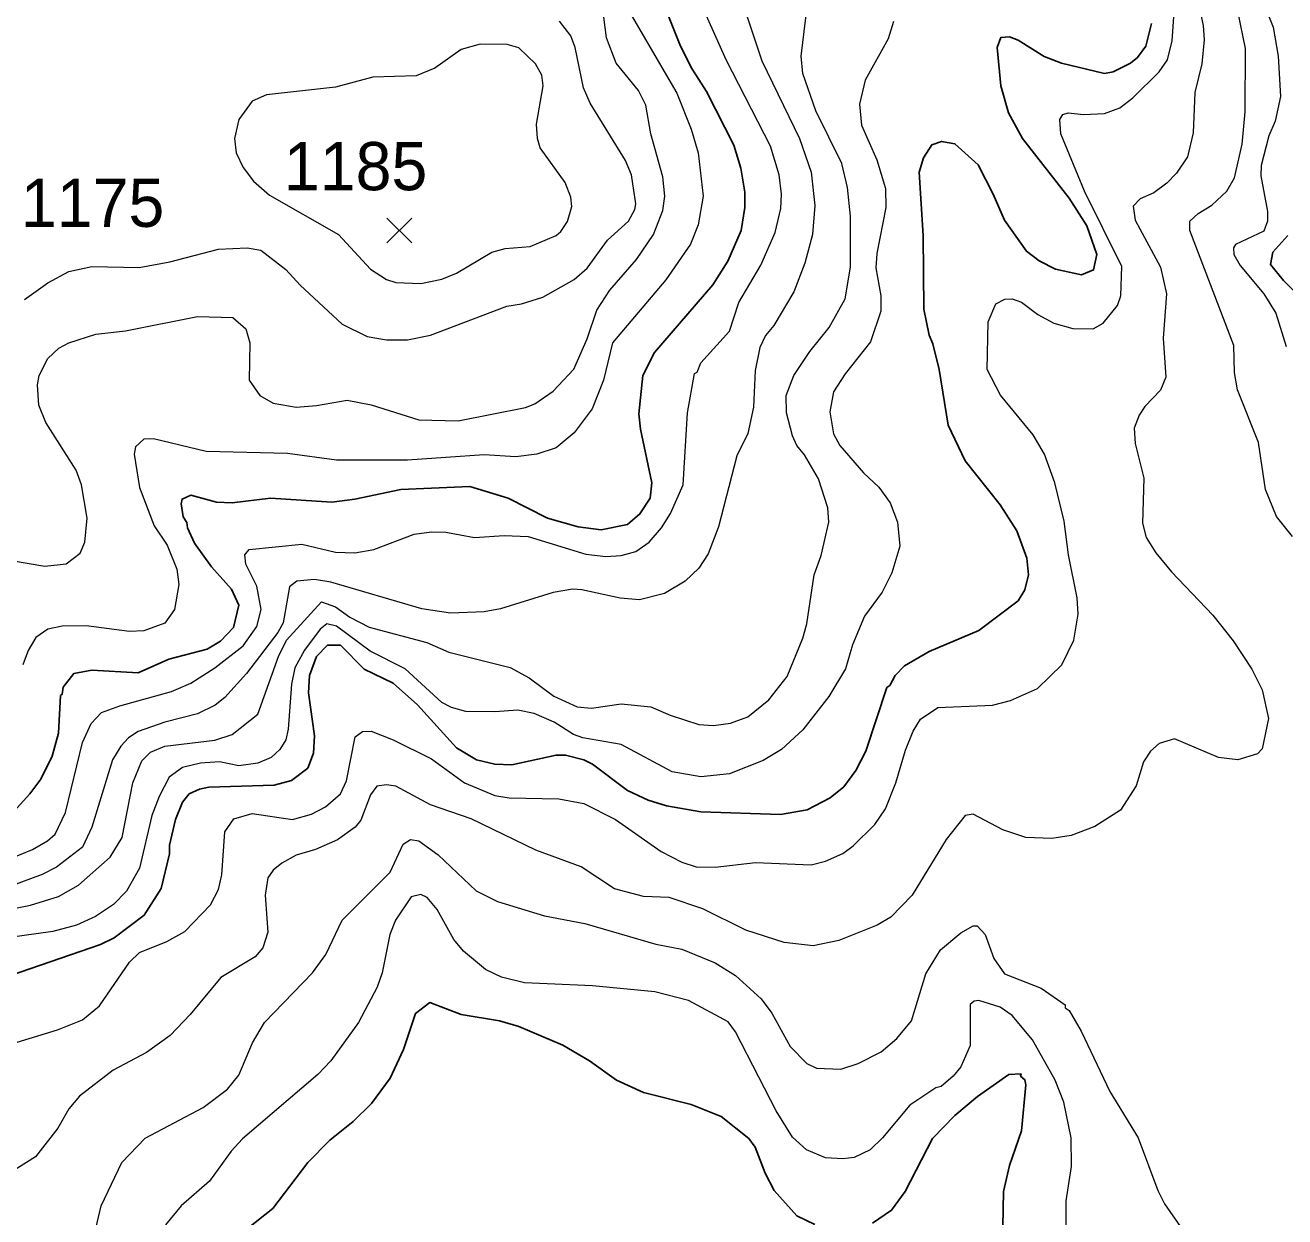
# Model space of a CAD drawing. Extents: x 265 to 291.4, y 7731.5 to 7759.6.
# Drawn here: x 287.12 to 289.21, y 7740.103 to 7742.081 of the extents above; entities that cross this region are included whole.
import ezdxf
from ezdxf.enums import TextEntityAlignment as Align

# ---------------------------------------------------------------- set-up
doc = ezdxf.new("R2010")
doc.units = 0
doc.header["$LTSCALE"] = 0.032
for name, color, linetype, lineweight in [('1', 7, 'Continuous', 25), ('2', 7, 'Continuous', 13), ('21', 7, 'Continuous', 25), ('61', 7, 'Continuous', 13)]:
    doc.layers.add(name, color=color, linetype=linetype, lineweight=lineweight)

msp = doc.modelspace()

# ---------------------------------------------------------------- linework, layer by layer
at = {"layer": '1'}
for points in [[(288.1811, 7742.1121), (288.2065, 7742.0485), (288.2256, 7742.0103), (288.2511, 7741.9705), (288.2964, 7741.8814), (288.3076, 7741.8432)], [(287.5908, 7740.973), (287.5924, 7741.0016), (287.6036, 7741.0334), (287.6219, 7741.0517), (287.6434, 7741.0517), (287.6831, 7741.0119), (287.7309, 7740.9888), (287.7714, 7740.9531), (287.8359, 7740.8815), (287.8693, 7740.8616), (287.8995, 7740.8544), (287.9281, 7740.8536), (288.0013, 7740.8695), (288.0172, 7740.8695), (288.0475, 7740.8616), (288.0618, 7740.8544), (288.1199, 7740.8106), (288.1541, 7740.7947), (288.1843, 7740.7852), (288.2416, 7740.7756), (288.3736, 7740.7709), (288.4182, 7740.7788), (288.4563, 7740.7987), (288.4786, 7740.817), (288.4985, 7740.8441), (288.5152, 7740.8759), (288.5502, 7740.9817), (288.555, 7740.9849), (288.5637, 7741.0016), (288.5796, 7741.0175), (288.6202, 7741.0413), (288.703, 7741.0763), (288.7682, 7741.1257), (288.7793, 7741.144), (288.7849, 7741.1686), (288.7825, 7741.1965), (288.7658, 7741.2418), (288.7379, 7741.2848), (288.6799, 7741.358), (288.652, 7741.4168), (288.6369, 7741.5091), (288.6266, 7741.5521), (288.6202, 7741.5664), (288.6114, 7741.6093), (288.6106, 7741.7318), (288.6035, 7741.8369), (288.6107, 7741.8607), (288.625, 7741.8822), (288.6409, 7741.8877), (288.6632, 7741.8838), (288.7014, 7741.8488), (288.7268, 7741.8003), (288.7451, 7741.7573), (288.7817, 7741.7056), (288.8031, 7741.6897), (288.8302, 7741.6761), (288.8732, 7741.6666), (288.8931, 7741.6746), (288.8986, 7741.7), (288.8819, 7741.7478), (288.8525, 7741.7939), (288.7753, 7741.8925), (288.7522, 7741.9355), (288.7395, 7741.98), (288.7332, 7742.0437), (288.7395, 7742.0604), (288.7539, 7742.0612), (288.7682, 7742.0556), (288.8111, 7742.0285), (288.8398, 7742.0174), (288.9114, 7742.0007), (288.9257, 7742.0031), (288.9543, 7742.0174), (288.9662, 7742.027), (288.9798, 7742.046), (288.9893, 7742.0835)], [(288.3076, 7741.8432), (288.3147, 7741.8034), (288.3147, 7741.778), (288.3084, 7741.7398), (288.2861, 7741.6889), (288.2614, 7741.6499), (288.1644, 7741.5377)], [(289.2152, 7741.7318), (289.1906, 7741.704), (289.1866, 7741.6833), (289.2081, 7741.6571), (289.2542, 7741.6109)], [(288.1644, 7741.5377), (288.1453, 7741.4996), (288.1389, 7741.4359), (288.1413, 7741.4105), (288.1604, 7741.3214), (288.1572, 7741.2959), (288.1405, 7741.2697), (288.1198, 7741.2521), (288.0761, 7741.2434), (288.0379, 7741.2482), (287.987, 7741.2625), (287.9218, 7741.2959), (287.8581, 7741.315), (287.7436, 7741.3102), (287.6672, 7741.2943), (287.629, 7741.2895), (287.5272, 7741.2959), (287.4636, 7741.2879), (287.4381, 7741.2895), (287.3952, 7741.3007), (287.3808, 7741.2943), (287.3792, 7741.2864), (287.3824, 7741.2649), (287.3888, 7741.2553), (287.3896, 7741.2466), (287.4015, 7741.2211), (287.4294, 7741.1822), (287.4628, 7741.1448), (287.4747, 7741.1185), (287.4659, 7741.0811), (287.4445, 7741.0588), (287.4222, 7741.0453), (287.3586, 7741.0286), (287.3077, 7741.0063), (287.2313, 7741.0103), (287.2011, 7741.0047), (287.1835, 7740.9825), (287.182, 7740.9706), (287.1788, 7740.9682), (287.1756, 7740.9061), (287.1653, 7740.868), (287.1462, 7740.8298), (287.1279, 7740.8051), (287.038, 7740.7064)], [(287.4254, 7740.8162), (287.5336, 7740.8194), (287.5622, 7740.8274), (287.5892, 7740.8481), (287.5988, 7740.8727), (287.6004, 7740.9014), (287.5908, 7740.973)], [(287.0961, 7740.5036), (287.2456, 7740.5553), (287.2679, 7740.5664), (287.318, 7740.6038), (287.3458, 7740.6484), (287.3601, 7740.7057), (287.3601, 7740.72), (287.3697, 7740.7629), (287.3816, 7740.7916), (287.3928, 7740.8051), (287.4095, 7740.813), (287.4254, 7740.8162)], [(288.4309, 7740.0907), (288.4007, 7740.1051), (288.3632, 7740.1472), (288.3481, 7740.1759), (288.3314, 7740.2188), (288.3211, 7740.2332), (288.275, 7740.2697), (288.2257, 7740.2896), (288.1461, 7740.3095), (288.1016, 7740.3302), (288.057, 7740.362), (288.0125, 7740.3882), (287.9393, 7740.4193), (287.9075, 7740.4288), (287.8438, 7740.4392), (287.7921, 7740.459), (287.7682, 7740.4408), (287.7483, 7740.3811), (287.7261, 7740.3334), (287.695, 7740.2912), (287.6648, 7740.2618), (287.6259, 7740.2307), (287.5892, 7740.1934), (287.5312, 7740.117), (287.489, 7740.0836)], [(288.7427, 7740.0868), (288.7435, 7740.1457), (288.7538, 7740.1886), (288.7737, 7740.2459), (288.7809, 7740.3222), (288.7793, 7740.331), (288.7721, 7740.3366), (288.773, 7740.3405), (288.7523, 7740.3397), (288.7006, 7740.3031), (288.6632, 7740.2713), (288.6258, 7740.2332), (288.5804, 7740.1457), (288.5581, 7740.1146), (288.5264, 7740.0931)]]:
    msp.add_lwpolyline(points, dxfattribs=at)
at = {"layer": '2'}
for points in [[(288.8406, 7741.0191), (288.8604, 7741.0605), (288.8676, 7741.1034), (288.866, 7741.1305), (288.8517, 7741.2021), (288.8445, 7741.2577), (288.8286, 7741.3214), (288.8119, 7741.3691), (288.7928, 7741.4009), (288.7387, 7741.4669), (288.7165, 7741.5091), (288.7181, 7741.5887), (288.7308, 7741.6181), (288.7459, 7741.626), (288.7578, 7741.6268), (288.7737, 7741.6213), (288.8008, 7741.6006), (288.827, 7741.5863), (288.8589, 7741.5775), (288.8923, 7741.5767), (288.909, 7741.5863), (288.9328, 7741.6157), (288.9384, 7741.6316), (288.94, 7741.6801), (288.8779, 7741.805), (288.839, 7741.9005), (288.8374, 7741.9244), (288.8421, 7741.9323), (288.8509, 7741.9355), (288.8764, 7741.9323), (288.9114, 7741.9339), (288.9368, 7741.9434), (288.9583, 7741.9601), (289.002, 7742.0031), (289.0156, 7742.023), (289.0235, 7742.0548), (289.0315, 7742.1662)], [(289.0561, 7742.1678), (289.0752, 7742.0803), (289.0768, 7742.0564), (289.0728, 7742.0166), (289.0609, 7741.9689), (289.0585, 7741.9021), (289.049, 7741.8623), (289.0307, 7741.8353), (289.0148, 7741.8185), (288.9933, 7741.8026), (288.9702, 7741.7923), (288.9591, 7741.7804), (288.9623, 7741.7573), (289.0044, 7741.6793), (289.014, 7741.6348), (289.0084, 7741.5616), (289.0132, 7741.4964), (289.0044, 7741.4749), (288.9782, 7741.4478), (288.9686, 7741.4335), (288.9607, 7741.4121), (288.9623, 7741.3866), (288.9766, 7741.3293), (288.9742, 7741.2546), (288.9806, 7741.2307)], [(287.0897, 7740.6953), (287.1327, 7740.7128), (287.1573, 7740.7271), (287.17, 7740.7383), (287.1875, 7740.7741), (287.2154, 7740.8902), (287.2297, 7740.922), (287.2472, 7740.9403), (287.2774, 7740.9515), (287.3634, 7740.9753), (287.3952, 7740.9888), (287.4349, 7741.0143), (287.4819, 7741.0509), (287.5049, 7741.0827), (287.5121, 7741.1114), (287.5049, 7741.1496), (287.4866, 7741.1861), (287.4851, 7741.2021), (287.4922, 7741.2108), (287.5797, 7741.2195), (287.6354, 7741.206), (287.6672, 7741.2052), (287.699, 7741.2108), (287.7659, 7741.2362), (287.7945, 7741.2402), (287.8184, 7741.2394), (287.8661, 7741.2307), (287.9154, 7741.2339), (287.9552, 7741.2323), (288.0507, 7741.2028), (288.0841, 7741.1989), (288.1095, 7741.2005), (288.1334, 7741.2076), (288.1557, 7741.2227), (288.1763, 7741.2466), (288.1914, 7741.2705), (288.2121, 7741.3182), (288.2193, 7741.4375), (288.2312, 7741.5027), (288.2352, 7741.5051), (288.2416, 7741.5202), (288.2893, 7741.5728), (288.3044, 7741.6205), (288.341, 7741.6825), (288.3649, 7741.7366), (288.3744, 7741.7764), (288.3752, 7741.8003), (288.3712, 7741.8321), (288.3569, 7741.8798), (288.2837, 7742.023), (288.2225, 7742.1598)], [(288.3076, 7742.1264), (288.3426, 7742.0214), (288.4054, 7741.8925), (288.4245, 7741.8369), (288.4309, 7741.7812), (288.4269, 7741.7334), (288.4142, 7741.6857), (288.3959, 7741.638), (288.3625, 7741.5823), (288.3489, 7741.5656), (288.3394, 7741.5457), (288.3314, 7741.5075), (288.3291, 7741.4471), (288.3195, 7741.4033), (288.3012, 7741.3659), (288.271, 7741.2482), (288.2535, 7741.2036), (288.2384, 7741.1798), (288.2153, 7741.1583), (288.1811, 7741.1376), (288.1397, 7741.1273), (288.1079, 7741.1297), (288.0443, 7741.144), (288.0284, 7741.1448), (287.9966, 7741.1392), (287.9091, 7741.1122), (287.882, 7741.1074), (287.8263, 7741.105), (287.7786, 7741.1122), (287.6275, 7741.1567), (287.6004, 7741.1607), (287.571, 7741.1583), (287.559, 7741.1488), (287.5487, 7741.0891), (287.5399, 7741.0732), (287.4874, 7741.0048), (287.4516, 7740.965), (287.4357, 7740.9523), (287.4063, 7740.9379), (287.3522, 7740.9244), (287.3077, 7740.9085), (287.2918, 7740.8982), (287.279, 7740.8846), (287.2655, 7740.8616), (287.2313, 7740.7502), (287.2154, 7740.7168), (287.1724, 7740.6834)], [(287.4636, 7740.9037), (287.5065, 7740.9372), (287.5407, 7741.0334), (287.5542, 7741.0604), (287.6123, 7741.1241), (287.6354, 7741.1153), (287.6593, 7741.0986), (287.6911, 7741.0819), (287.7866, 7741.0565), (287.8231, 7741.0406), (287.925, 7741.0151), (287.9568, 7740.9976), (287.9974, 7740.9674), (288.0363, 7740.9499), (288.0602, 7740.9475), (288.1095, 7740.9546), (288.1588, 7740.9499), (288.1907, 7740.9356), (288.2384, 7740.9204), (288.2623, 7740.9188), (288.2909, 7740.9228), (288.3195, 7740.9332), (288.3545, 7740.961), (288.3847, 7741), (288.411, 7741.0636), (288.4174, 7741.0875), (288.4293, 7741.1686), (288.4412, 7741.2005), (288.454, 7741.2561), (288.4524, 7741.28), (288.4365, 7741.3277), (288.4134, 7741.3675), (288.4006, 7741.3834), (288.3935, 7741.3993), (288.3839, 7741.4375), (288.3831, 7741.4662), (288.3959, 7741.4996), (288.4221, 7741.5393), (288.4547, 7741.5791), (288.481, 7741.6268), (288.4898, 7741.6793), (288.4898, 7741.7637), (288.485, 7741.8114), (288.4754, 7741.8512), (288.4325, 7741.9387), (288.411, 7742.0007), (288.4078, 7742.0294), (288.4205, 7742.1344)], [(289.1723, 7742.1248), (289.1914, 7742.0771), (289.1993, 7742.0294), (289.2033, 7741.9625), (289.1945, 7741.9212), (289.1842, 7741.8973), (289.1715, 7741.848), (289.1707, 7741.8305), (289.1818, 7741.7716), (289.1818, 7741.7557), (289.1755, 7741.739), (289.1285, 7741.7167), (289.1253, 7741.7112), (289.1261, 7741.7), (289.1365, 7741.6817), (289.1755, 7741.6348), (289.1953, 7741.603), (289.2128, 7741.5473)], [(287.0977, 7741.1925), (287.1533, 7741.1829), (287.1883, 7741.1869), (287.2114, 7741.2044), (287.2194, 7741.2227), (287.2233, 7741.2625), (287.2138, 7741.3182), (287.205, 7741.3421), (287.1549, 7741.4216), (287.143, 7741.4502), (287.1406, 7741.4837), (287.1438, 7741.4996), (287.1581, 7741.5274), (287.1764, 7741.5449), (287.1931, 7741.5537), (287.2377, 7741.568), (287.287, 7741.5735), (287.4063, 7741.5974), (287.4652, 7741.5958), (287.4866, 7741.5767), (287.493, 7741.5537), (287.4922, 7741.4916), (287.5097, 7741.4661), (287.532, 7741.4534), (287.5702, 7741.4471), (287.6036, 7741.4494), (287.6545, 7741.4582), (287.6943, 7741.451), (287.7738, 7741.4256), (287.8391, 7741.424), (287.9504, 7741.4463), (287.9663, 7741.4526), (287.9966, 7741.4733), (288.0308, 7741.5099), (288.053, 7741.56), (288.0689, 7741.6078), (288.0904, 7741.6412), (288.135, 7741.6921), (288.1628, 7741.7334), (288.1787, 7741.7732), (288.1819, 7741.7971), (288.1787, 7741.8289), (288.1588, 7741.9005), (288.1501, 7741.9482), (288.1381, 7741.9721), (288.1008, 7742.0174), (288.0848, 7742.0596), (288.0777, 7742.1153)], [(288.1151, 7742.1169), (288.2018, 7741.9681), (288.2257, 7741.9084), (288.2368, 7741.8687), (288.2455, 7741.7971), (288.2368, 7741.7493), (288.2241, 7741.7175), (288.1835, 7741.6579), (288.0952, 7741.5537), (288.0801, 7741.4916), (288.061, 7741.4439), (288.0315, 7741.4041), (288.0013, 7741.3794), (287.9695, 7741.3691), (287.9345, 7741.3643), (287.882, 7741.3675), (287.7547, 7741.3588), (287.637, 7741.3588), (287.5559, 7741.3699), (287.4206, 7741.3731), (287.3331, 7741.3945), (287.3172, 7741.3938), (287.3037, 7741.381), (287.3013, 7741.3691), (287.31, 7741.3134), (287.3347, 7741.2498), (287.3562, 7741.218), (287.3721, 7741.1782), (287.3753, 7741.1527), (287.3681, 7741.1114), (287.3522, 7741.0883), (287.3172, 7741.0756), (287.2934, 7741.0748), (287.2218, 7741.0843), (287.182, 7741.0835), (287.1581, 7741.0787), (287.1382, 7741.0644), (287.1255, 7741.043), (287.1167, 7741.0191)], [(289.2232, 7741.2323), (289.1969, 7741.2657), (289.1786, 7741.3102), (289.1667, 7741.3882), (289.1317, 7741.4757), (289.1269, 7741.5043), (289.1261, 7741.5489), (289.053, 7741.7398), (289.053, 7741.7557), (289.0665, 7741.7684), (289.0896, 7741.7819), (289.1142, 7741.805), (289.1269, 7741.8273), (289.1397, 7741.883), (289.1444, 7741.9371), (289.1452, 7742.0421), (289.1325, 7742.1041)], [(288.5613, 7742.0866), (288.5526, 7742.058), (288.5144, 7741.9896), (288.5049, 7741.9498), (288.508, 7741.9148), (288.5335, 7741.8575), (288.5478, 7741.8098), (288.5486, 7741.778), (288.5335, 7741.7016), (288.5319, 7741.6778), (288.5399, 7741.6316), (288.5399, 7741.6062), (288.5232, 7741.5553), (288.481, 7741.5019), (288.4619, 7741.4725), (288.4555, 7741.4391), (288.4619, 7741.4025), (288.4722, 7741.3834), (288.5112, 7741.3381), (288.5367, 7741.3142), (288.5558, 7741.288), (288.5677, 7741.2561), (288.5717, 7741.2164), (288.5582, 7741.1718), (288.5422, 7741.14), (288.5128, 7741.1002), (288.4929, 7741.0525), (288.4818, 7741.0127), (288.454, 7740.9666), (288.411, 7740.9117), (288.3752, 7740.8791), (288.345, 7740.8608), (288.2893, 7740.8385), (288.2416, 7740.8337), (288.1938, 7740.8417), (288.1095, 7740.887), (288.0459, 7740.8982), (288.03, 7740.9037), (287.9981, 7740.9244), (287.9647, 7740.9387), (287.9377, 7740.9443), (287.8995, 7740.9411), (287.8518, 7740.9419), (287.8279, 7740.9483), (287.812, 7740.957), (287.7508, 7741.0127), (287.6927, 7741.0421), (287.637, 7741.0835), (287.6211, 7741.0875)], [(287.9196, 7741.6145), (287.944, 7741.6181), (287.9791, 7741.6292), (288.0316, 7741.6586), (288.053, 7741.6777), (288.0864, 7741.7239), (288.1214, 7741.7557), (288.1318, 7741.7748), (288.1334, 7741.7843), (288.1262, 7741.8321), (288.1167, 7741.8559), (288.0578, 7741.9514), (288.0467, 7741.9769), (288.0331, 7742.0437), (288.026, 7742.0628), (288.0069, 7742.0874)], [(287.1191, 7741.6253), (287.1581, 7741.6531), (287.1931, 7741.6722), (287.2313, 7741.6801), (287.3093, 7741.6785), (287.3602, 7741.6881), (287.4413, 7741.7088), (287.489, 7741.7112), (287.5113, 7741.7072), (287.5527, 7741.6754), (287.5765, 7741.6491), (287.6465, 7741.5847), (287.6879, 7741.564), (287.7197, 7741.5584), (287.7547, 7741.5584), (287.7929, 7741.5664), (287.9196, 7741.6145)], [(288.9806, 7741.2307), (288.9965, 7741.2052), (289.0227, 7741.1734), (289.0911, 7741.1018), (289.1245, 7741.0589), (289.1556, 7741.0119), (289.1731, 7740.9777)], [(287.6211, 7741.0875), (287.6099, 7741.0787), (287.5837, 7741.0437), (287.5678, 7741.0143), (287.5622, 7740.9873), (287.5566, 7740.9125), (287.5527, 7740.895)], [(288.594, 7740.9093), (288.6059, 7740.9292), (288.6345, 7740.9483), (288.7252, 7740.9523), (288.7555, 7740.9602), (288.8, 7740.9801), (288.8406, 7741.0191)], [(289.1731, 7740.9777), (289.1834, 7740.93), (289.1731, 7740.8799), (289.1651, 7740.8719), (289.1325, 7740.8616), (289.1007, 7740.8656), (289.0275, 7740.8966), (289.0021, 7740.8886), (288.9877, 7740.8759), (288.9758, 7740.8584), (288.9639, 7740.8186), (288.9376, 7740.778), (288.8955, 7740.751), (288.8557, 7740.7359), (288.8239, 7740.7311), (288.7809, 7740.7327), (288.7427, 7740.7454), (288.6934, 7740.7717), (288.6799, 7740.7693), (288.6488, 7740.7295), (288.5924, 7740.6373), (288.5566, 7740.6007), (288.5343, 7740.5871), (288.4707, 7740.5617), (288.4277, 7740.5529), (288.38, 7740.5585), (288.3163, 7740.5792), (288.2448, 7740.6142), (288.1891, 7740.6333), (288.1461, 7740.6349), (288.0984, 7740.6476), (288.0427, 7740.6842), (287.9679, 7740.712), (287.8605, 7740.7637), (287.7929, 7740.7868), (287.7356, 7740.8178), (287.7197, 7740.8202), (287.7038, 7740.8178), (287.6935, 7740.8035), (287.6776, 7740.7614), (287.668, 7740.7502), (287.6386, 7740.7287), (287.602, 7740.7128), (287.5702, 7740.7033), (287.5463, 7740.6905), (287.532, 7740.6786), (287.5232, 7740.6659), (287.5185, 7740.6373), (287.5232, 7740.576), (287.5145, 7740.5498), (287.5018, 7740.5346), (287.4453, 7740.5004), (287.3944, 7740.4392), (287.361, 7740.4042), (287.322, 7740.3763), (287.2663, 7740.3469), (287.2106, 7740.3039), (287.1931, 7740.2825), (287.1748, 7740.2507), (287.1374, 7740.2029), (287.077, 7740.1655)], [(287.5527, 7740.895), (287.5431, 7740.8791), (287.5288, 7740.8656), (287.5065, 7740.856), (287.4747, 7740.852), (287.4429, 7740.8584), (287.4111, 7740.856), (287.3816, 7740.8488), (287.3594, 7740.833), (287.3427, 7740.8011), (287.3307, 7740.7693), (287.31, 7740.6818), (287.2886, 7740.6436), (287.2671, 7740.6214), (287.2369, 7740.6015), (287.2058, 7740.5871), (287.1661, 7740.5768), (287.0913, 7740.5664)], [(287.1072, 7740.393), (287.174, 7740.4137), (287.2154, 7740.4304), (287.244, 7740.4535), (287.2933, 7740.5259), (287.31, 7740.5418), (287.3554, 7740.5601), (287.3856, 7740.5768), (287.4278, 7740.6213), (287.4413, 7740.6468), (287.4469, 7740.6707), (287.4516, 7740.7423), (287.4667, 7740.7637), (287.497, 7740.7725), (287.5638, 7740.7629), (287.5956, 7740.7717), (287.6187, 7740.7836), (287.6434, 7740.8051), (287.6537, 7740.8266), (287.668, 7740.8998), (287.6799, 7740.9085), (287.6943, 7740.9093), (287.7309, 7740.895), (287.7945, 7740.8632), (287.8494, 7740.8234), (287.8995, 7740.8027), (287.9234, 7740.7987), (288.0061, 7740.7971), (288.0475, 7740.7892), (288.1, 7740.7629), (288.1755, 7740.7096), (288.2098, 7740.6921), (288.2336, 7740.6842), (288.2654, 7740.6834), (288.3323, 7740.6913), (288.4245, 7740.6874), (288.4484, 7740.6937), (288.477, 7740.7065), (288.4945, 7740.7192), (288.5303, 7740.7542), (288.5478, 7740.7804), (288.5653, 7740.8234), (288.5812, 7740.8775), (288.594, 7740.9093)], [(287.2814, 7740.7327), (287.2989, 7740.8234), (287.314, 7740.86), (287.3284, 7740.8743), (287.3522, 7740.8846), (287.4349, 7740.8942), (287.4636, 7740.9037)], [(287.0818, 7740.611), (287.1295, 7740.6205), (287.1756, 7740.6349), (287.209, 7740.6539), (287.2615, 7740.7001), (287.2814, 7740.7327)], [(287.2201, 7740.0088), (287.2464, 7740.1218), (287.2806, 7740.1934), (287.3196, 7740.2339), (287.4159, 7740.2848), (287.4564, 7740.3151), (287.4747, 7740.3382), (287.4978, 7740.3923), (287.5177, 7740.4257), (287.5972, 7740.5084), (287.6195, 7740.5386), (287.6465, 7740.5959), (287.7261, 7740.6754), (287.7476, 7740.7216), (287.7595, 7740.7295), (287.7738, 7740.7271), (287.8056, 7740.7041), (287.8685, 7740.6444), (287.9043, 7740.6269), (287.9822, 7740.603), (288.0491, 7740.5903), (288.1668, 7740.5561), (288.2098, 7740.5474), (288.2654, 7740.5251), (288.2988, 7740.5036), (288.3418, 7740.4654), (288.3593, 7740.4416), (288.3895, 7740.3859), (288.4174, 7740.358), (288.4333, 7740.3501), (288.4739, 7740.3485), (288.5025, 7740.358), (288.5407, 7740.3771), (288.5669, 7740.3994), (288.5908, 7740.4288), (288.6146, 7740.5068), (288.6393, 7740.5466), (288.6727, 7740.5744), (288.6934, 7740.5863), (288.6998, 7740.5863), (288.7133, 7740.572), (288.7276, 7740.5323), (288.7451, 7740.5068), (288.8064, 7740.4829), (288.8461, 7740.4551), (288.8461, 7740.4503), (288.8525, 7740.4455), (288.8724, 7740.4113), (288.9201, 7740.3111), (288.967, 7740.2347), (288.9997, 7740.1472), (289.0108, 7740.125), (289.041, 7740.0812)], [(287.1724, 7740.6834), (287.1486, 7740.6715), (287.0802, 7740.646), (287.0277, 7740.6166), (286.968, 7740.5696), (286.9075, 7740.5139), (286.8845, 7740.4988)], [(288.8477, 7740.082), (288.8477, 7740.1297), (288.8565, 7740.187), (288.8557, 7740.2347), (288.8437, 7740.2936), (288.8294, 7740.3302), (288.792, 7740.397), (288.7578, 7740.4376), (288.7379, 7740.4511), (288.703, 7740.4622), (288.695, 7740.4614), (288.6886, 7740.4559), (288.6886, 7740.3875), (288.6727, 7740.3525), (288.66, 7740.3366), (288.6401, 7740.3198), (288.6313, 7740.3175), (288.5884, 7740.2888), (288.543, 7740.2347), (288.5224, 7740.2148), (288.4961, 7740.2021), (288.477, 7740.1997), (288.4484, 7740.2013), (288.4166, 7740.2148), (288.3935, 7740.2355), (288.3664, 7740.2793), (288.2988, 7740.4105), (288.2869, 7740.4272), (288.2209, 7740.4622), (288.1652, 7740.4766), (288.0618, 7740.4869), (287.9488, 7740.4917), (287.9106, 7740.5012), (287.8844, 7740.5139), (287.8478, 7740.5442), (287.8319, 7740.5633), (287.804, 7740.6134), (287.7873, 7740.6333), (287.777, 7740.638), (287.7611, 7740.6341), (287.7348, 7740.5959), (287.7253, 7740.572), (287.7126, 7740.5084), (287.7046, 7740.4845), (287.6736, 7740.4257), (287.6274, 7740.362), (287.606, 7740.3397), (287.4811, 7740.2331), (287.462, 7740.2125), (287.4262, 7740.1624), (287.3793, 7740.1218), (287.353, 7740.09)]]:
    msp.add_lwpolyline(points, dxfattribs=at)
msp.add_lwpolyline([(287.9167, 7741.7102), (287.9584, 7741.7135), (288.0013, 7741.7318), (288.0093, 7741.7382), (288.0204, 7741.7549), (288.0276, 7741.7796), (288.026, 7741.7955), (288.0164, 7741.8194), (287.9751, 7741.8774), (287.9703, 7741.8925), (287.9687, 7741.9164), (287.9798, 7741.98), (287.9775, 7741.9975), (287.9671, 7742.0166), (287.9393, 7742.0429), (287.9202, 7742.0484), (287.8756, 7742.0492), (287.8438, 7742.0405), (287.8001, 7742.0095), (287.7691, 7741.9967), (287.6975, 7741.9943), (287.6354, 7741.9776), (287.5209, 7741.9649), (287.497, 7741.9546), (287.4747, 7741.9244), (287.4675, 7741.8925), (287.4707, 7741.8687), (287.4819, 7741.8448), (287.4994, 7741.8217), (287.5256, 7741.7987), (287.6402, 7741.7334), (287.6935, 7741.6761), (287.7197, 7741.6586), (287.7356, 7741.6539), (287.777, 7741.6523), (287.812, 7741.6594), (287.8359, 7741.669), (287.8947, 7741.704)], close=True, dxfattribs=at)
at = {"layer": '21'}
for p, q in [((287.7207, 7741.7606), (287.7619, 7741.7194)), ((287.7619, 7741.7606), (287.7207, 7741.7194))]:
    msp.add_line(p, q, dxfattribs=at)

# ---------------------------------------------------------------- texts
at = {"layer": '61'}
for s, p in [('1185', (287.6687, 7741.8068)), ('1175', (287.2323, 7741.746))]:
    msp.add_text(s, height=0.08, dxfattribs=at).set_placement(p, align=Align.CENTER)

doc.saveas('drawing.dxf')
